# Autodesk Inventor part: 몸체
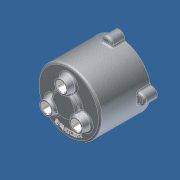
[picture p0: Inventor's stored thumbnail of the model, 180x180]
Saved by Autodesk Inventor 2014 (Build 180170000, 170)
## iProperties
Created: 2012-05
Part Number: 몸체
Document SubType Name: 모델링
Designer: SeoGD™
Material: 알루미늄 6061
Appearance: 알루미늄 - 평지
Density: 1 g/cm^3
변환 표준: STEP AP214IS
파일 이름: C:\Users\SeoGD\Desktop\?쒗뿕\紐몄껜.stp
전처리기: Build: 253, Release: 2010 SP1 - Date: Wed 07/29/2009
전송 단위: 밀리미터
불확실성: 0.01
Author: SeoGD™
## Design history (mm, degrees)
sketch "스케치2"
  geometry: C1 r 50 at (0, 0); 1 further point
  constraints: 1 centre point, 1 coincident
  dimensions: "d9" = 100 diameter of C1
extrude "돌출2" new body sketch "스케치2" distance "d10" = 80; taper "d11" = 0 deg
feature "쉘1" dims "d12" = 5
sketch "스케치3" dims "d13" = 55
  geometry: C1 r 7.5 at (0, 27.5); C2 r 12.5 at (0, 27.5); 2 further points
  constraints: 2 centre point, 2 coincident, 2 vertical alignment, 2 other
  dimensions: "d14" = 15 diameter of C1; "d15" = 25 diameter of C2
extrude "돌출3" join sketch "스케치3" distance "d16" = 12; taper "d17" = -10 deg
hole "구멍2" diameter "d20" = 15; stored, may be unused: countersink angle "d24" = 90 deg, drill point angle "d26" = 118 deg; dims "d18" = 10, "d19" = 10, "d21" = 6, "d22" = 4, "d23" = 2, "d25" = 15
chamfer "모따기1" distance "d27" = 1; stored, may be unused: second distance "d28" = 2, angle "d29" = 45 deg
sketch "스케치4"
  geometry: L1 (0, 0)-(0, 88); L2 (0, 70)-(13.16, 70); L3 (-45, 75)-(45, 75) reference; L4 (-50, 80)-(50, 80) reference; L5 (13.16, 70)-(14.5, 75); L6 (20, 80)-(20, 88); L7 (20, 88)-(0, 88); L8 (20, 80)-(14.5, 75)
  constraints: 12 end point, 3 point on line, 2 perpendicular, 1 vertical
  dimensions: "d34" = 40 diameter of L6 L1; "d35" = 105 deg angle of L5 L3; "d36" = 5 distance between parallel lines of L2 L3; "d37" = 8 distance between parallel lines of L7 L4; "d51" = 29 diameter of L5.end L1
revolve "회전1" sketch "스케치4" stored, may be unused: angle "d38" = 90 deg
hole "구멍3" diameter "d41" = 15; stored, may be unused: countersink angle "d45" = 90 deg, drill point angle "d47" = 0 deg; dims "d39" = 10, "d40" = 10, "d42" = 6, "d43" = 22, "d44" = 13, "d46" = 15
chamfer "모따기2" distance "d48" = 1; stored, may be unused: second distance "d49" = 2, angle "d50" = 45 deg
fillet "모깎기1" dims "d52" = 3
fillet "모깎기2" dims "d53" = 3, "d72" = 0.2
sketch "스케치5"
  geometry: A1 r 50 centre (0, 0) between (50, 0) and (-8.074, 49.344) reference; A2 r 8.5 centre (0, 52) between (8.074, 49.344) and (-8.074, 49.344); 1 further point
  constraints: 5 point on circle, 1 centre point, 1 horizontal alignment
  dimensions: "d54" = 90 deg dimension on point (0, 0) A2.centre A1.start; "d55" = 52 distance of A2.centre point (0, 0); "d56" = 17 diameter of A2
extrude "돌출4" join sketch "스케치5" distance "d57" = 20; taper "d58" = 0 deg
fillet "모깎기3" dims "d59" = 3
hole "구멍4" diameter "d62" = 4.134; stored, may be unused: countersink angle "d66" = 90 deg, drill point angle "d68" = 118 deg; dims "d60" = 10, "d61" = 10, "d63" = 12, "d64" = 22, "d65" = 13, "d67" = 15
sketch "스케치6"
  geometry: C1 r 47 at (0, 0) reference; C2 r 42.5 at (0, 0); 1 further point
  constraints: 1 centre point, 1 coincident, 1 other
  dimensions: "d73" = 85 diameter of C2
feature "엠보싱1" sketch "스케치6" dims "d74" = 1, "d75" = 0
node "솔리드1"
node "솔리드 본체"
node "곡면 본체"
pattern_circular "원형 패턴1" dims "d31" = 360 deg
pattern_circular "원형 패턴2" dims "d70" = 360 deg
node "솔리드2"
